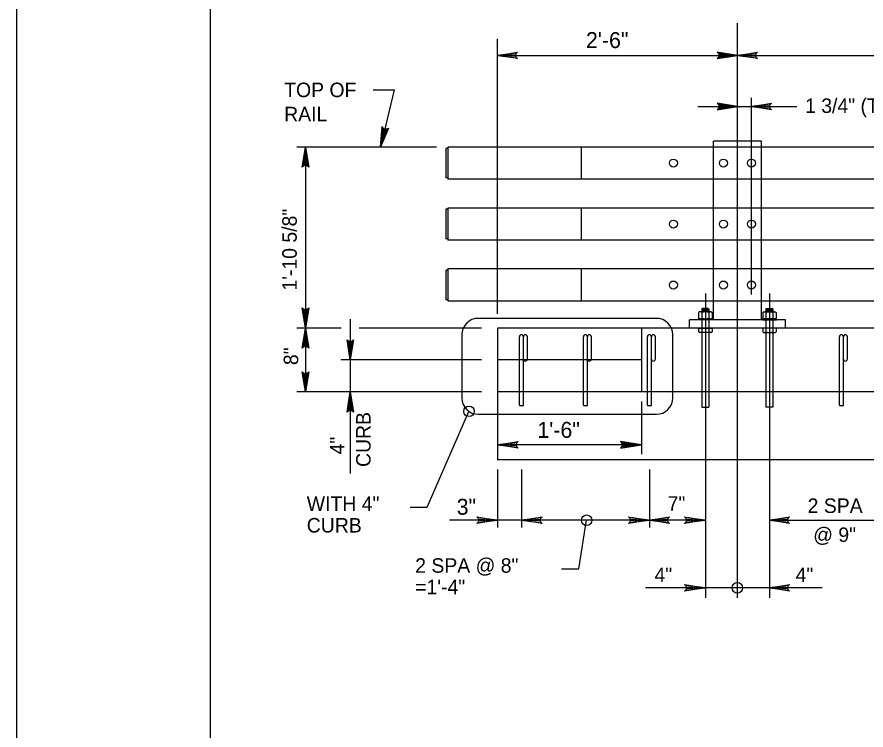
# Model space of a CAD drawing. Extents: x 641054 to 641910, y 298137 to 299325.
# Drawn here: x 641054.5 to 641229.9, y 299039.1 to 299186.5 of the extents above; entities that cross this region are included whole.
import ezdxf

# ---------------------------------------------------------------- set-up
doc = ezdxf.new("R2010")
doc.units = 0
for name, color, linetype in [('1', 7, 'Continuous'), ('2', 7, 'Continuous'), ('Default', 7, 'Continuous'), ('PLT-BNDY', 7, 'Continuous')]:
    doc.layers.add(name, color=color, linetype=linetype)

msp = doc.modelspace()

# ---------------------------------------------------------------- linework, layer by layer
at = {"layer": '1'}
for p, q in [((641195.55, 299125.57), (641195.36, 299125.46)), ((641195.36, 299125.46), (641195.36, 299124.25)), ((641197.96, 299125.57), (641195.55, 299125.57)), ((641196.03, 299126.17), (641196.15, 299126.29)), ((641196.03, 299126.17), (641196.03, 299125.57)), ((641197.47, 299126.17), (641196.03, 299126.17)), ((641197.47, 299125.81), (641196.03, 299125.81)), ((641196.03, 299125.77), (641196.03, 299105.88)), ((641196.03, 299125.46), (641196.03, 299124.25)), ((641197.36, 299125.99), (641196.14, 299125.99)), ((641197.36, 299125.63), (641196.14, 299125.63)), ((641197.35, 299126.29), (641196.15, 299126.29)), ((641197.47, 299126.17), (641197.35, 299126.29)), ((641197.47, 299126.17), (641197.47, 299125.57)), ((641197.47, 299125.77), (641197.47, 299105.88)), ((641197.47, 299125.46), (641197.47, 299124.25)), ((641197.96, 299125.57), (641198.14, 299125.46)), ((641198.14, 299125.46), (641198.14, 299124.25)), ((641208.77, 299125.57), (641208.59, 299125.46)), ((641208.59, 299125.46), (641208.59, 299124.25)), ((641208.77, 299125.57), (641211.18, 299125.57)), ((641209.25, 299126.17), (641209.37, 299126.29)), ((641209.25, 299126.17), (641209.25, 299125.57)), ((641209.25, 299126.17), (641210.7, 299126.17)), ((641209.25, 299125.81), (641210.7, 299125.81)), ((641209.25, 299125.77), (641209.25, 299105.88)), ((641209.25, 299125.46), (641209.25, 299124.25)), ((641209.37, 299126.29), (641210.58, 299126.29)), ((641209.37, 299125.99), (641210.58, 299125.99)), ((641209.37, 299125.63), (641210.58, 299125.63)), ((641210.7, 299126.17), (641210.58, 299126.29)), ((641210.7, 299126.17), (641210.7, 299125.57)), ((641210.7, 299125.77), (641210.7, 299105.88)), ((641210.7, 299125.46), (641210.7, 299124.25)), ((641211.18, 299125.57), (641211.37, 299125.46)), ((641211.37, 299125.46), (641211.37, 299124.25)), ((641195.55, 299124.14), (641195.36, 299124.25)), ((641197.96, 299124.14), (641198.14, 299124.25)), ((641208.77, 299124.14), (641208.59, 299124.25)), ((641211.18, 299124.14), (641211.37, 299124.25)), ((641195.36, 299122.24), (641195.36, 299121.45)), ((641195.36, 299122.24), (641198.14, 299122.24)), ((641196.03, 299122.24), (641196.03, 299121.45)), ((641197.47, 299122.24), (641197.47, 299121.45)), ((641198.14, 299122.24), (641198.14, 299121.45)), ((641208.59, 299122.24), (641208.59, 299121.45)), ((641211.37, 299122.24), (641208.59, 299122.24)), ((641209.25, 299122.24), (641209.25, 299121.45)), ((641210.7, 299122.24), (641210.7, 299121.45)), ((641211.37, 299122.24), (641211.37, 299121.45)), ((641195.55, 299121.34), (641195.36, 299121.45)), ((641197.96, 299121.34), (641195.55, 299121.34)), ((641197.96, 299121.34), (641198.14, 299121.45)), ((641208.77, 299121.34), (641208.59, 299121.45)), ((641208.77, 299121.34), (641211.18, 299121.34)), ((641211.18, 299121.34), (641211.37, 299121.45)), ((641196.03, 299105.88), (641197.47, 299105.88)), ((641210.7, 299105.88), (641209.25, 299105.88))]:
    msp.add_line(p, q, dxfattribs=at)
for points in [[(641195.3, 299123.9), (641195.3, 299124.14), (641198.2, 299124.14), (641198.2, 299123.9)], [(641211.42, 299123.9), (641211.42, 299124.14), (641208.53, 299124.14), (641208.53, 299123.9)]]:
    msp.add_lwpolyline(points, close=True, dxfattribs=at)
for points in [[(641157.85, 299097.6), (641157.69, 299097.9), (641153.76, 299098.11), (641157.85, 299097.6), (641158.06, 299097.42), (641153.76, 299098.11), (641157.69, 299098.31), (641157.83, 299098.6), (641153.76, 299098.11), (641158.06, 299098.8), (641157.83, 299098.6)], [(641179.44, 299097.6), (641179.59, 299097.9), (641183.52, 299098.11), (641179.44, 299097.6), (641179.23, 299097.42), (641183.52, 299098.11), (641179.59, 299098.31), (641179.45, 299098.6), (641183.52, 299098.11), (641179.23, 299098.8), (641179.45, 299098.6)], [(641181.09, 299083.01), (641181.24, 299082.72), (641185.17, 299082.5), (641181.09, 299083.01), (641180.88, 299083.19), (641185.17, 299082.5), (641181.24, 299082.31), (641181.1, 299082.01), (641185.17, 299082.5), (641180.88, 299081.82), (641181.1, 299082.01)], [(641192.66, 299083.01), (641192.81, 299082.72), (641196.75, 299082.5), (641192.66, 299083.01), (641192.45, 299083.19), (641196.75, 299082.5), (641192.82, 299082.31), (641192.67, 299082.01), (641196.75, 299082.5), (641192.45, 299081.82), (641192.67, 299082.01)], [(641162.81, 299081.99), (641162.65, 299082.28), (641158.72, 299082.5), (641162.81, 299081.99), (641163.02, 299081.81), (641158.72, 299082.5), (641162.65, 299082.7), (641162.8, 299082.99), (641158.72, 299082.5), (641163.02, 299083.18), (641162.8, 299082.99)], [(641192.66, 299069.03), (641192.81, 299068.73), (641196.75, 299068.52), (641192.66, 299069.03), (641192.45, 299069.21), (641196.75, 299068.52), (641192.82, 299068.32), (641192.67, 299068.03), (641196.75, 299068.52), (641192.45, 299067.83), (641192.67, 299068.03)]]:
    msp.add_lwpolyline(points, dxfattribs=at)
for centre, radius, start, end in [((641195.69, 299124.99), 0.573, 54.2983, 90.0007), ((641196.75, 299123.08), 2.48, 73.0665, 106.9347), ((641197.81, 299124.99), 0.573, 90.0001, 125.7026), ((641208.92, 299124.99), 0.573, 54.2974, 89.9999), ((641209.98, 299123.08), 2.48, 73.0653, 106.9335), ((641211.03, 299124.99), 0.573, 89.9993, 125.7017), ((641195.69, 299124.72), 0.573, 270.0017, 305.7041), ((641196.75, 299126.63), 2.48, 253.0683, 286.9366), ((641197.81, 299124.72), 0.573, 234.299, 270.0015), ((641208.92, 299124.72), 0.573, 269.9985, 305.701), ((641209.98, 299126.63), 2.48, 253.0634, 286.9317), ((641211.03, 299124.72), 0.573, 234.2959, 269.9983), ((641195.69, 299121.91), 0.573, 270.0017, 305.7041), ((641196.75, 299123.82), 2.48, 253.0683, 286.9366), ((641197.81, 299121.91), 0.573, 234.299, 270.0015), ((641208.92, 299121.91), 0.573, 269.9985, 305.701), ((641209.98, 299123.82), 2.48, 253.0634, 286.9317), ((641211.03, 299121.91), 0.573, 234.2959, 269.9983)]:
    msp.add_arc(centre, radius, start, end, dxfattribs=at)
at = {"layer": '2'}
for p, q in [((641094.49, 298746.38), (641094.49, 299310.38)), ((641143.11, 299159.38), (641143.11, 299153.29)), ((641143.53, 299159.38), (641143.11, 299159.38)), ((641143.53, 299159.65), (641143.53, 299153.04)), ((641375.12, 299159.65), (641143.53, 299159.65)), ((641171.08, 299159.65), (641171.08, 299153.04)), ((641143.53, 299153.29), (641143.11, 299153.29)), ((641375.12, 299153.04), (641143.53, 299153.04)), ((641143.53, 299146.78), (641143.11, 299146.78)), ((641143.11, 299146.78), (641143.11, 299140.69)), ((641143.53, 299147.05), (641143.53, 299140.43)), ((641375.12, 299147.05), (641143.53, 299147.05)), ((641171.08, 299147.05), (641171.08, 299140.43)), ((641143.53, 299140.69), (641143.11, 299140.69)), ((641375.12, 299140.43), (641143.53, 299140.43)), ((641143.53, 299134.17), (641143.11, 299134.17)), ((641143.11, 299134.17), (641143.11, 299128.08)), ((641143.53, 299134.44), (641143.53, 299127.83)), ((641375.12, 299134.44), (641143.53, 299134.44)), ((641171.08, 299134.44), (641171.08, 299127.83)), ((641143.53, 299128.08), (641143.11, 299128.08)), ((641375.12, 299127.82), (641143.53, 299127.82)), ((641158.31, 299106.23), (641159.13, 299106.23)), ((641171.53, 299106.23), (641172.36, 299106.23)), ((641184.76, 299106.23), (641185.59, 299106.23)), ((641224.45, 299106.23), (641225.27, 299106.23))]:
    msp.add_line(p, q, dxfattribs=at)
for points in [[(641157.73, 299178.11), (641157.59, 299178.4), (641153.76, 299178.61), (641157.73, 299178.11), (641157.94, 299177.94), (641153.76, 299178.61), (641157.58, 299178.8), (641157.72, 299179.09), (641153.76, 299178.61), (641157.94, 299179.28), (641157.72, 299179.09)], [(641199.39, 299178.11), (641199.54, 299178.4), (641203.36, 299178.61), (641199.39, 299178.11), (641199.19, 299177.94), (641203.36, 299178.61), (641199.54, 299178.8), (641199.4, 299179.09), (641203.36, 299178.61), (641199.19, 299179.28), (641199.4, 299179.09)], [(641207.34, 299178.11), (641207.19, 299178.4), (641203.36, 299178.61), (641207.34, 299178.11), (641207.54, 299177.94), (641203.36, 299178.61), (641207.19, 299178.8), (641207.33, 299179.09), (641203.36, 299178.61), (641207.54, 299179.28), (641207.33, 299179.09)], [(641199.39, 299167.56), (641199.54, 299167.84), (641203.36, 299168.06), (641199.39, 299167.56), (641199.19, 299167.38), (641203.36, 299168.06), (641199.54, 299168.25), (641199.4, 299168.53), (641203.36, 299168.06), (641199.19, 299168.72), (641199.4, 299168.53)], [(641210.23, 299167.56), (641210.08, 299167.84), (641206.26, 299168.06), (641210.23, 299167.56), (641210.44, 299167.38), (641206.26, 299168.06), (641210.08, 299168.25), (641210.22, 299168.53), (641206.26, 299168.06), (641210.44, 299168.72), (641210.22, 299168.53)], [(641131.04, 299163.4), (641130.72, 299163.33), (641129.63, 299159.65), (641131.04, 299163.4), (641131.26, 299163.56), (641129.63, 299159.65), (641130.33, 299163.41), (641130.09, 299163.62), (641129.63, 299159.65), (641129.95, 299163.87), (641130.09, 299163.62)], [(641113.62, 299155.68), (641113.9, 299155.83), (641114.12, 299159.65), (641113.62, 299155.68), (641113.44, 299155.48), (641114.12, 299159.65), (641114.3, 299155.83), (641114.59, 299155.69), (641114.12, 299159.65), (641114.78, 299155.48), (641114.59, 299155.69)], [(641114.61, 299126.22), (641114.33, 299126.07), (641114.12, 299122.24), (641114.61, 299126.22), (641114.79, 299126.42), (641114.12, 299122.24), (641113.93, 299126.07), (641113.64, 299126.21), (641114.12, 299122.24), (641113.45, 299126.42), (641113.64, 299126.21)], [(641113.62, 299118.27), (641113.9, 299118.42), (641114.12, 299122.24), (641113.62, 299118.27), (641113.44, 299118.07), (641114.12, 299122.24), (641114.3, 299118.42), (641114.59, 299118.28), (641114.12, 299122.24), (641114.78, 299118.07), (641114.59, 299118.28)], [(641123.87, 299119.6), (641123.58, 299119.45), (641123.37, 299115.63), (641123.87, 299119.6), (641124.04, 299119.81), (641123.37, 299115.63), (641123.18, 299119.45), (641122.9, 299119.59), (641123.37, 299115.63), (641122.71, 299119.81), (641122.9, 299119.59)], [(641114.61, 299112.99), (641114.33, 299112.84), (641114.12, 299109.02), (641114.61, 299112.99), (641114.79, 299113.19), (641114.12, 299109.02), (641113.93, 299112.84), (641113.64, 299112.98), (641114.12, 299109.02), (641113.45, 299113.19), (641113.64, 299112.98)], [(641122.87, 299105.04), (641123.16, 299105.19), (641123.37, 299109.02), (641122.87, 299105.04), (641122.7, 299104.84), (641123.37, 299109.02), (641123.56, 299105.19), (641123.84, 299105.05), (641123.37, 299109.02), (641124.03, 299104.84), (641123.84, 299105.05)], [(641149.74, 299083), (641149.89, 299082.71), (641153.71, 299082.5), (641149.74, 299083), (641149.54, 299083.17), (641153.71, 299082.5), (641149.89, 299082.31), (641149.75, 299082.03), (641153.71, 299082.5), (641149.54, 299081.84), (641149.75, 299082.03)], [(641189.15, 299082), (641189, 299082.29), (641185.17, 299082.5), (641189.15, 299082), (641189.35, 299081.83), (641185.17, 299082.5), (641189, 299082.69), (641189.14, 299082.97), (641185.17, 299082.5), (641189.35, 299083.17), (641189.14, 299082.97)], [(641213.95, 299082), (641213.81, 299082.29), (641209.98, 299082.5), (641213.95, 299082), (641214.16, 299081.83), (641209.98, 299082.5), (641213.8, 299082.69), (641213.94, 299082.97), (641209.98, 299082.5), (641214.16, 299083.17), (641213.94, 299082.97)], [(641213.95, 299068.02), (641213.81, 299068.3), (641209.98, 299068.52), (641213.95, 299068.02), (641214.16, 299067.84), (641209.98, 299068.52), (641213.8, 299068.7), (641213.94, 299068.99), (641209.98, 299068.52), (641214.16, 299069.18), (641213.94, 299068.99)]]:
    msp.add_lwpolyline(points, dxfattribs=at)
for centre in [(641147.89, 299105.01), (641172.21, 299082.5), (641203.36, 299068.52)]:
    msp.add_circle(centre, 1.09, dxfattribs=at)
at = {"layer": 'Default'}
for p, q in [((641203.36, 299066.46), (641203.36, 299185.26)), ((641153.76, 299125.19), (641153.76, 299182.03)), ((641153.76, 299178.61), (641327.38, 299178.61)), ((641206.26, 299129.18), (641206.26, 299169.81)), ((641195.18, 299168.06), (641215.62, 299168.06)), ((641198.41, 299159.65), (641198.41, 299160.89)), ((641208.33, 299160.89), (641198.41, 299160.89)), ((641208.33, 299159.65), (641208.33, 299160.89)), ((641141.21, 299159.65), (641112.34, 299159.65)), ((641114.12, 299159.65), (641114.12, 299109.02)), ((641198.41, 299153.04), (641198.41, 299159.65)), ((641208.33, 299153.04), (641208.33, 299159.65)), ((641198.41, 299147.05), (641198.41, 299153.04)), ((641208.33, 299147.05), (641208.33, 299153.04)), ((641198.41, 299140.43), (641198.41, 299147.05)), ((641208.33, 299140.43), (641208.33, 299147.05)), ((641198.41, 299134.44), (641198.41, 299140.43)), ((641208.33, 299134.44), (641208.33, 299140.43)), ((641198.41, 299127.83), (641198.41, 299134.44)), ((641208.33, 299127.83), (641208.33, 299134.44)), ((641196.75, 299129.37), (641196.75, 299066.46)), ((641209.98, 299129.37), (641209.98, 299066.46)), ((641198.41, 299123.9), (641198.41, 299127.82)), ((641208.33, 299123.9), (641208.33, 299127.82)), ((641114.12, 299126.21), (641114.12, 299124.23)), ((641123.37, 299124.08), (641123.37, 299092.19)), ((641213.28, 299123.9), (641193.44, 299123.9)), ((641193.44, 299122.24), (641193.44, 299123.9)), ((641213.28, 299122.24), (641213.28, 299123.9)), ((641121.5, 299122.24), (641112.34, 299122.24)), ((641150.45, 299122.24), (641125.19, 299122.24)), ((641153.76, 299122.24), (641153.76, 299094.96)), ((641375.12, 299122.24), (641153.76, 299122.24)), ((641183.52, 299122.24), (641183.52, 299109.02)), ((641158.31, 299106.23), (641158.31, 299120.43)), ((641159.13, 299106.23), (641159.13, 299120.43)), ((641159.96, 299115.82), (641159.96, 299120.43)), ((641171.53, 299106.23), (641171.53, 299120.43)), ((641172.36, 299106.23), (641172.36, 299120.43)), ((641173.19, 299115.82), (641173.19, 299120.43)), ((641184.76, 299106.23), (641184.76, 299120.43)), ((641185.59, 299106.23), (641185.59, 299120.43)), ((641186.41, 299115.82), (641186.41, 299120.43)), ((641224.45, 299106.23), (641224.45, 299120.43)), ((641225.27, 299106.23), (641225.27, 299120.43)), ((641226.1, 299115.82), (641226.1, 299120.43)), ((641158.31, 299118.12), (641158.31, 299118.95)), ((641171.53, 299118.12), (641171.53, 299118.95)), ((641184.76, 299118.12), (641184.76, 299118.95)), ((641224.45, 299118.12), (641224.45, 299118.95)), ((641150.45, 299115.63), (641121.38, 299115.63)), ((641183.52, 299115.63), (641153.76, 299115.63)), ((641158.31, 299114.61), (641158.31, 299115.43)), ((641171.53, 299114.61), (641171.53, 299115.43)), ((641184.76, 299114.61), (641184.76, 299115.43)), ((641224.45, 299114.61), (641224.45, 299115.43)), ((641150.45, 299109.02), (641112.34, 299109.02)), ((641150.45, 299109.02), (641120.42, 299109.02)), ((641375.12, 299109.02), (641153.76, 299109.02)), ((641183.52, 299107.03), (641183.52, 299096.15)), ((641139.27, 299085.19), (641147.89, 299105.01)), ((641183.52, 299098.11), (641153.76, 299098.11)), ((641375.12, 299094.96), (641153.76, 299094.96)), ((641153.76, 299092.98), (641153.76, 299080.98)), ((641158.72, 299092.98), (641158.72, 299080.98)), ((641185.17, 299092.98), (641185.17, 299080.98)), ((641135.74, 299085.19), (641139.27, 299085.19)), ((641196.75, 299082.5), (641143.89, 299082.5)), ((641170.57, 299072.42), (641172.21, 299082.5)), ((641209.98, 299082.5), (641320.76, 299082.5)), ((641167.04, 299072.42), (641170.57, 299072.42)), ((641220.86, 299068.52), (641184.37, 299068.52))]:
    msp.add_line(p, q, dxfattribs=at)
for points in [[(641128.08, 299171.51), (641132.45, 299171.51), (641129.63, 299159.65)], [(641186.62, 299124.24), (641149.82, 299124.24)], [(641146.45, 299120.87), (641146.45, 299107.77)], [(641189.99, 299107.77), (641189.99, 299120.87)], [(641149.82, 299104.4), (641186.62, 299104.4)]]:
    msp.add_lwpolyline(points, dxfattribs=at)
for centre in [(641190.14, 299156.34), (641200.47, 299156.34), (641206.26, 299156.34), (641190.14, 299143.73), (641200.47, 299143.73), (641206.26, 299143.73), (641190.14, 299131.13), (641200.47, 299131.13), (641206.26, 299131.13)]:
    msp.add_circle(centre, 0.826, dxfattribs=at)
for centre, radius, start, end in [((641149.82, 299120.87), 3.37, 90, 180), ((641186.62, 299120.87), 3.37, 0, 90), ((641158.72, 299120.43), 0.413, 0, 180), ((641159.55, 299120.43), 0.413, 0, 180), ((641171.95, 299120.43), 0.413, 0, 180), ((641172.77, 299120.43), 0.413, 0, 180), ((641185.17, 299120.43), 0.413, 0, 180), ((641186, 299120.43), 0.413, 0, 180), ((641224.86, 299120.43), 0.413, 0, 180), ((641225.69, 299120.43), 0.413, 0, 180), ((641159.55, 299115.82), 0.413, 180, 0), ((641172.77, 299115.82), 0.413, 180, 0), ((641186, 299115.82), 0.413, 180, 0), ((641225.69, 299115.82), 0.413, 180, 0), ((641149.82, 299107.77), 3.37, 180, 270), ((641186.62, 299107.77), 3.37, 270, 0)]:
    msp.add_arc(centre, radius, start, end, dxfattribs=at)
at = {"layer": 'PLT-BNDY'}
msp.add_lwpolyline([(641054.49, 299325.38), (641895.49, 299325.38), (641895.49, 298731.38), (641054.49, 298731.38)], close=True, dxfattribs=at)

# ---------------------------------------------------------------- texts
at = {"layer": '2'}
for s, height, p in [('2\'-6"', 3.3, (641172.07, 299180.12)), ('TOP OF', 3, (641109.7, 299169.97)), ('RAIL', 3, (641109.7, 299164.97)), ('1\'-6"', 3.3, (641162.03, 299099.53)), ('WITH 4"', 3, (641114.37, 299084.41)), ('3"', 3.3, (641145.35, 299083.63)), ('7"', 3, (641188.95, 299084.47)), ('2 SPA', 3, (641217.88, 299084)), ('CURB', 3, (641114.37, 299079.96)), ('@ 9"', 3, (641219.04, 299078)), ('2 SPA @ 8"', 3, (641136.78, 299071.64)), ('4"', 3, (641186.23, 299069.71)), ('4"', 3, (641215.39, 299069.71)), ('=1\'-4"', 3, (641136.78, 299067.2))]:
    msp.add_text(s, height=height, dxfattribs=at).set_placement(p)
for s, rotation, p in [('1 3/4" (TYP)', 360, (641217.35, 299166.7)), ('1\'-10 5/8"', 90, (641112.31, 299129.98)), ('8"', 90, (641112.6, 299114.57)), ('CURB', 90, (641127.57, 299093.51)), ('4"', 90, (641122.17, 299096.1))]:
    msp.add_text(s, height=3, rotation=rotation, dxfattribs=at).set_placement(p)

doc.saveas('drawing.dxf')
